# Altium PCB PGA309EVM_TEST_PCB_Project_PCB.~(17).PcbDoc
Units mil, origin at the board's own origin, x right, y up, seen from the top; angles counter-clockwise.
Board outline 6000 x 1500 mil, 2 copper layers (Top Layer, Bottom Layer), stack 62 mil thick; 101 components, 66 nets, 270 pads, 32 vias.
Unrouted connection lines stored in the file: 1.
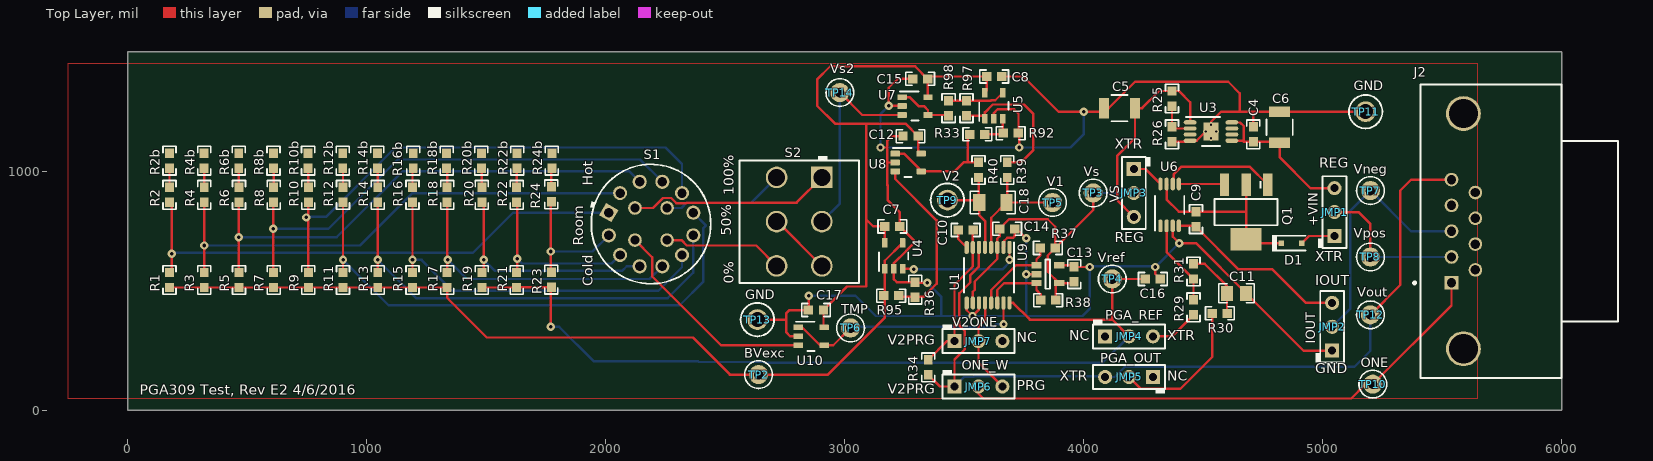
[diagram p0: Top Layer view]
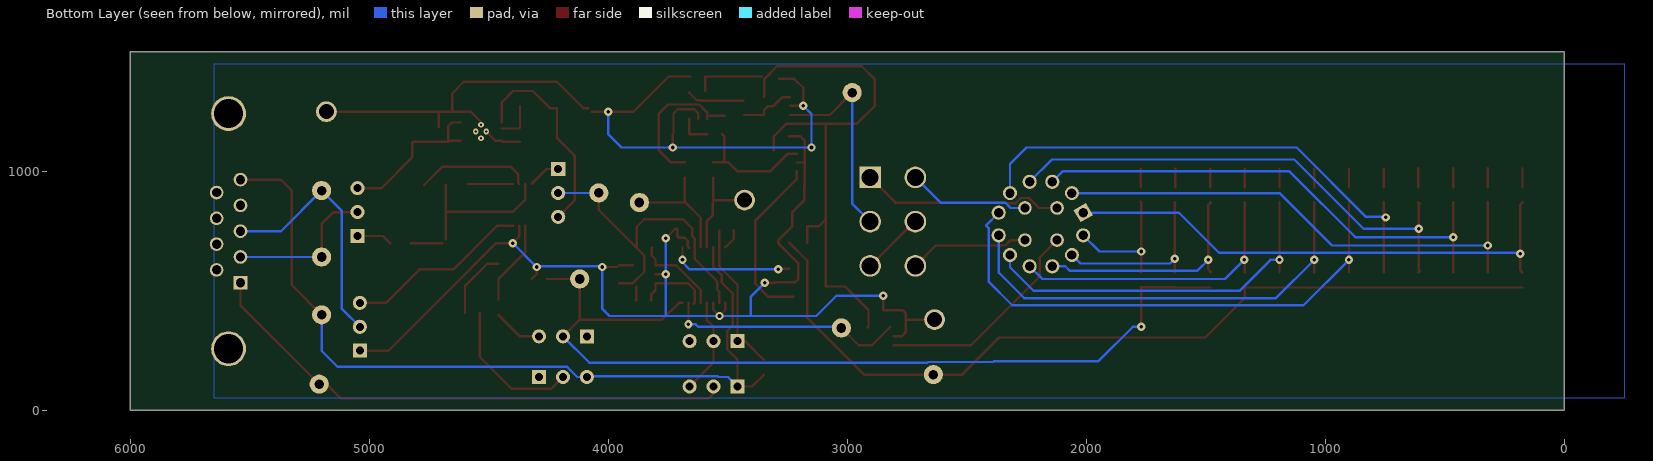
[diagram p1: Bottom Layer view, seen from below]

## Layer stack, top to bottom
Top Layer: signal copper 1.4
Dielectric: core 59.2, FR-4, Dk 4.8
Bottom Layer: signal copper 1.4

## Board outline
0,0 6000,0 6000,1500 0,1500

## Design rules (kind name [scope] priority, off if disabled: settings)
AcuteAngle [All] p1: minimum=4.50000000000000E+0001 checktracksonly=FALSE
AssemblyTestPointUsage [All] p1: valid=2
Clearance Clearance_Keepouts [((IsTrack Or IsArc) And Not InPoly) And IsFree and IsKeepOut vs ((IsTrack Or IsArc) And Not InPoly) And IsFree and IsKeepOut] p1: gap=0
Clearance Clearance_Poly [InPolygon] p2: gap=25
Clearance [All] p3: gap=7.87
ComponentClearance ComponentClearance_MountingHoles_FiducialMarks [InComponentClass('Mounting Holes') vs InComponentClass('FiducialMark')] p1: gap=50 collisioncheckmode=3 verticalgap=10 showdistances=FALSE
ComponentClearance ComponentClearance_Shunt [InComponentClass('Header') vs InComponentClass('Shunt')] p2: gap=0 collisioncheckmode=3 verticalgap=0 showdistances=FALSE
ComponentClearance ComponentClearance_Logo [InComponentClass('Logo')] p3: gap=50 collisioncheckmode=3 verticalgap=10 showdistances=FALSE
ComponentClearance ComponentClearance_ScrewToNut [(HasFootprint('NY PMS 440 0025 PH')) vs (HasFootprint('Keystone_1902C'))] p4: gap=5 collisioncheckmode=3 verticalgap=10 showdistances=FALSE
ComponentClearance ComponentClearance_MountingHoles [InComponentClass('Mounting Holes')] p5: gap=250 collisioncheckmode=3 verticalgap=100000 showdistances=FALSE
ComponentClearance ComponentClearance_SmallPassives [HasFootprint('0201*') or HasFootprint('0402*') or HasFootprint('0508') or HasFootprint('0603*') or HasFootprint('0612') or HasFootprint('0805*') or HasFootprint('0815*') or HasFootprint('0830*') or HasFootprint('1206*') or HasFootprint('1210*') or HasFootprint('1808*') or HasFootprint('1812*') or HasFootprint('1825*') or HasFootprint('2010*') or HasFootprint('2220*') or HasFootprint('2225*') or HasFootprint('2512*') or HasFootprint('2728*') or HasFootprint('3518*') vs HasFootprint('0201*') or HasFootprint('0402*') or HasFootprint('0508') or HasFootprint('0603*') or HasFootprint('0612') or HasFootprint('0805*') or HasFootprint('0815*') or HasFootprint('0830*') or HasFootprint('1206*') or HasFootprint('1210*') or HasFootprint('1808*') or HasFootprint('1812*') or HasFootprint('1825*') or HasFootprint('2010*') or HasFootprint('2220*') or HasFootprint('2225*') or HasFootprint('2512*') or HasFootprint('2728*') or HasFootprint('3518*')] p6: gap=14.96 collisioncheckmode=3 verticalgap=10 showdistances=FALSE
ComponentClearance ComponentClearance_THtoSMT [IsThruComponent vs IsSMTComponent] p7: gap=40 collisioncheckmode=3 verticalgap=30 showdistances=FALSE
ComponentClearance ComponentClearance_THtoTH [IsThruComponent vs IsThruComponent] p8: gap=30 collisioncheckmode=3 verticalgap=30 showdistances=FALSE
ComponentClearance [All] p9: gap=30 collisioncheckmode=3 verticalgap=10 showdistances=FALSE
DiffPairsRouting [All] p1: maxlimit=100 minlimit=10 mostfreqgap=10 maxuncoupledlength=1000
FabricationTestPointUsage TestPointUsage [All] p1: valid=2 allowmultiple=FALSE
FabricationTestpoint Testpoint [All] p1: side=3 testpointundercomponent=TRUE minsize=40 maxsize=100 preferedsize=60 minholesize=0 maxholesize=40 preferedholesize=32 testpointgrid=1 allowsidetop=TRUE allowsidebottom=TRUE usegrid=TRUE gridtolerance=0.01
FanoutControl Fanout_LCC [IsLCC] p1: bgadir=Out bgaviamode=Centered fanoutstyle=Auto fanoutdirection=Alternating viagrid=1 // Fanout_LCC (Default Rule)
FanoutControl Fanout_BGA [IsBGA] p2: bgadir=Out bgaviamode=Centered fanoutstyle=Auto fanoutdirection=Alternating viagrid=1 // Fanout_BGA (Default Rule)
FanoutControl Fanout_Default [All] p4: bgadir=Out bgaviamode=Centered fanoutstyle=Auto fanoutdirection=Alternating viagrid=1 // Fanout_Default (Default Rule)
FanoutControl Fanout_Small [(CompPinCount < 5)] p5: bgadir=Out bgaviamode=Centered fanoutstyle=Auto fanoutdirection=OutThenIn viagrid=1 // Fanout_Small (Default Rule)
HoleSize [All] p1: absolutevalues=TRUE maxlimit=251 minlimit=7.87 maxpercent=80.000 minpercent=20.000
MinimumAnnularRing MinimumAnnularRing_ThermalPadVias [IsVia and InAnyComponent] p1: minimumring=5.91
MinimumAnnularRing [All] p2: minimumring=8
MinimumSolderMaskSliver MinimumSolderMaskSliver_Logo [InComponentClass('Logo') vs InComponentClass('Logo')] p1: minsoldermaskwidth=0.7
MinimumSolderMaskSliver [All] p2: minsoldermaskwidth=3.94
PlaneConnect [All] p1: planeconnectstyle=Relief reliefexpansion=10 reliefentries=4 reliefconductorwidth=10 reliefairgap=10
PolygonConnect [All] p1: connectstyle=Relief reliefconductorwidth=10 reliefentries=4 polygonreliefangle="90 Angle" airgapwidth=10
RoutingVias ThermalPadVias [IsVia and InAnyComponent] p1: holewidth=7.87 width=19.68 viastyle="Through Hole" minholewidth=7.87 minwidth=19.68 maxholewidth=12.99 maxwidth=23.62
RoutingVias [All] p2: holewidth=16 width=34 viastyle="Through Hole" minholewidth=7.87 minwidth=26 maxholewidth=40 maxwidth=65
SilkToSilkClearance SilkToSilkClearance_Pb-FreeLogo [(HasFootprint('Pb-Free_Overlay_Medium') OR HasFootprint('Pb-Free_Overlay_Small')) vs (HasFootprint('Pb-Free_Overlay_Medium') OR HasFootprint('Pb-Free_Overlay_Small'))] p1: silktosilkclearance=0
SilkToSilkClearance [All] p2: silktosilkclearance=4
SilkscreenOverComponentPads SilkToComponentPadClearance [IsPad and InAnycomponent] p1: minsilkscreentomaskgap=5
SilkscreenOverComponentPads "Silk to Solder Mask Opening" [All] p2: minsilkscreentomaskgap=4
SolderMaskExpansion [All] p1: expansion=1.97
Width [All] p1: maxlimit=100 minlimit=6 preferedwidth=10 checkconnectedcopper=TRUE
14 further rules are at their usual default settings.

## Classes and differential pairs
component class Header: JMP1 JMP2 JMP3 JMP4 JMP5 JMP6 JMP7 JMP99

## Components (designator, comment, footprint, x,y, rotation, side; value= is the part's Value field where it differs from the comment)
C4 "C0603C104K5RACTU" 0603 4710,1155 r90 top
C5 "12103C106KAT2A" 1210_280 4150,1265 r180 top
C6 "12103C106KAT2A" 1210_280 4820,1185 r90 top
C7 "C0603C104K5RACTU" 0603 3200,770 r180 top
C8 "C0603C104K5RACTU" 0603 3625.87,1397.4 r0 top
C9 "C0603C103J5RACTU" 0603 4470,800 r270 top
C10 "06035A561JAT2A" 0603 3506.83,754.84 r0 top
C11 "08051C223JAT2A" 0805_HV 4640,490 r0 top
C12 "C0603C104K5RACTU" 0603 3275.87,1147.4 r0 top
C13 "C0603C104K5RACTU" 0603 3960.16,570 r270 top
C14 "C0603C104K5RACTU" 0603 3680,760 r180 top
C15 "C0603C104K5RACTU" 0603 3315.87,1387.4 r0 top
C16 "06033C101KAT2A" 0603 4290,550 r0 top
C17 "C0603C104K5RACTU" 0603 2880,420 r0 top
C18 "C3216C0G1E103J" 1206 3620,870 r180 top
D1 "ZHCS400TA" sod-323 4870,700 r0 top
J2 "09 65 162 6810" "Harting_09 65 162 6810" 6000,750 r90 top
JMP1 "+VIN" Mill-Max_800-10-003-10-001000 5050,830 r90 top
JMP2 "IOUT" Mill-Max_800-10-003-10-001000 5040,350 r90 top
JMP3 "VS" Mill-Max_800-10-003-10-001000 4210,910 r270 top
JMP4 "PGA_REF" Mill-Max_800-10-003-10-001000 4190,310 r0 top
JMP5 "PGA_OUT" Mill-Max_800-10-003-10-001000 4190,140 r180 top
JMP6 "ONE_W" Mill-Max_800-10-003-10-001000 3560,100 r0 top
JMP7 "V2ONE" Mill-Max_800-10-003-10-001000 3560,290 r0 top
Q1 "BCP55" SOT-223 4680,830 r270 top
R1 "CRCW060328K7FKEA" 0603 175.31,545.69 r90 top
R2 "CRCW06031K05FKEA" 0603 175.24,902.39 r270 top
R2b "0" 0603 175,1045 r270 top
R3 "CRCW060340K2FKEA" 0603 320.54,545.69 r90 top
R4 "CRCW06031K50FKEA" 0603 320.47,902.39 r270 top
R4b "0" 0603 320,1045 r270 top
R5 "CRCW060371K5FKEA" 0603 465.76,545.69 r90 top
R6 "CRCW06033K74FKEA" 0603 465.7,902.39 r270 top
R6b "0" 0603 465,1045 r270 top
R7 "CRCW060310K2FKEA" 0603 610.99,545.69 r90 top
R8 "CRCW06031K91FKEA" 0603 610.92,902.39 r270 top
R8b "0" 0603 610,1045 r270 top
R9 "RT0603BRD0719K3L" 0603 756.21,545.69 r90 top
R10 "CRCW06033K65FKEA" 0603 756.15,902.39 r270 top
R10b "0" 0603 755,1045 r270 top
R11 "CRCW060321K5FKEA" 0603 901.44,545.69 r90 top
R12 "CRCW06034K87FKEA" 0603 901.38,902.39 r270 top
R12b "0" 0603 900,1045 r270 top
R13 "CRCW060311K5FKEA" 0603 1046.67,545.69 r90 top
R14 "RT0603BRD074K37L" 0603 1046.6,902.39 r270 top
R14b "0" 0603 1045,1045 r270 top
R15 "CRCW060311K0FKEA" 0603 1191.89,545.69 r90 top
R16 "CRCW06034K22FKEA" 0603 1191.83,902.39 r270 top
R16b "0" 0603 1195,1045 r270 top
R17 "CRCW06031K05FKEA" 0603 1337.12,545.69 r90 top
R18 "RT0603BRD0723K4L" 0603 1337.05,902.39 r270 top
R18b "0" 0603 1335,1045 r270 top
R19 "CRCW060342K2FKEA" 0603 1482.35,545.69 r90 top
R20 "RT0603BRD077K96L" 0603 1482.28,902.39 r270 top
R20b "0" 0603 1480,1045 r270 top
R21 "RT0603BRD076K9L" 0603 1627.57,545.69 r90 top
R22 "CRCW06031K07FKEA" 0603 1627.51,902.39 r270 top
R22b "0" 0603 1630,1045 r270 top
R23 "CRCW060316K2FKEA" 0603 1772.8,546.99 r90 top
R24 "CPF0603B2K0E" 0603 1772.73,904 r270 top
R24b "0" 0603 1775,1045 r270 top
R25 "CRCW0603953KFKEA" 0603 4370,1305 r90 top
R26 "RT0603BRD07291KL" 0603 4370,1155 r90 top
R29 "CRCW0603191KFKEA" 0603 4460,431.5 r90 top
R30 "CRCW060311K3FKEA" 0603 4570,405.99 r0 top
R31 "CRCW060310K0FKEA" 0603 4460,581.5 r90 top
R33 "CRCW06031K00FKEA" 0603 3555,1155 r180 top
R34 "CRCW0603100RFKEA" 0603 3350,180 r270 top
R36 "CRCW060310K0FKEA" 0603 3295,505 r270 top
R37 "CRCW060310K0FKEA" 0603 3850,680 r0 top
R38 "CRCW060310K0FKEA" 0603 3851.81,461.3 r0 top
R39 "CRCW06031K00FKEA" 0603 3680.43,1006.14 r270 top
R40 "CRCW06031K00FKEA" 0603 3560.43,1006.14 r270 top
R92 "RT0603BRD07100KL" 0603 3695,1160 r0 top
R95 "CRCW060310K0FKEA" 0603 3195,480 r180 top
R97 "CRCW06031K00FKEA" 0603 3510,1265 r270 top
R98 "RT0603BRD07100KL" 0603 3435,1265 r270 top
S1 "56P30-01-4-03N" SW_56P30-01-4-03N 2190,780 r0 top
S2 "M2024SS1G03" SW_M2024 2810,790 r270 top
TP2 "BVexc" Keystone5000 2640,150 r0 top
TP3 "Vs" Keystone5000 4040,910 r0 top
TP4 "Vref" Keystone5000 4120,550 r0 top
TP5 "V1" Keystone5000 3870,870 r0 top
TP6 "TMP" Keystone5004 3025,345 r0 top
TP7 "Vneg" Keystone5004 5200,920 r0 top
TP8 "Vpos" Keystone5000 5200,642 r0 top
TP9 "V2" Keystone5006 3430,880 r0 top
TP10 "ONE" Keystone5000 5210,110 r0 top
TP11 "GND" Keystone5006 5180,1250 r0 top
TP12 "Vout" Keystone5000 5200,400 r0 top
TP13 "GND" Keystone5006 2635,380 r0 top
TP14 "Vs2" Keystone5000 2980,1330 r0 top
U1 "PGA309AIPWR" PW0016A_N 3600.43,566.14 r270 top
U3 "TPS7A1601DGNR" DGN0008C_N 4533,1167 r0 top
U4 "OPA333AMDBVREP" DBV0005A_N 3205.16,646.83 r90 top
U5 "OPA333AMDBVREP" DBV0005A_N 3624.45,1275.07 r90 top
U6 "XTR117AIDGKR" DGK0008A_N 4360,860 r90 top
U7 "OPA333AMDBVREP" DBV0005A_N 3294.8,1273.54 r0 top
U8 "OPA333AMDBVREP" DBV0005A_N 3265.87,1037.4 r0 top
U9 "24LC32AT-I/OT" SOT-23-5 3850.16,570 r0 top
U10 "OPA333AMDBVREP" DBV0005A_N 2860,310 r0 top

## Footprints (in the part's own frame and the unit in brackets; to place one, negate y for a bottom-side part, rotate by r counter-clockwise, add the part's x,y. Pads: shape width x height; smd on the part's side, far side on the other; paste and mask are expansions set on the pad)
0603 [mm] "0603 from SM-752 data"
  rect 1x0.95 smd: 1(-0.8,0) 2(0.8,0)
  silkscreen extent -1.52,-0.69 1.52,0.69, body extent -0.87,-0.47 0.87,0.47, height 1
0805_HV [mil] "0805 with 30mil clearance between pads"
  rect 50x63 smd: 1(-40,0) 2(40,0)
  silkscreen extent -74,-40 74,40, body extent -43,-29 43,29, height 57
1206 [mm] "1206 from SM-752 data"
  rect 1.3x1.85 smd: 1(-1.45,0) 2(1.45,0)
  silkscreen extent -2.4,-1.21 2.4,1.21, body extent -1.7,-0.9 1.7,0.9, height 1.35
1210_280 [mm] "SMD, 2-Leads, Body 3.6x2.8mm, Height 2.8mm"
  rect 1.1x2.2 smd: 1(-1.65,0) 2(1.65,0)
  silkscreen extent -0.84,-1.4 0.84,1.4, body extent -1.8,-1.4 1.8,1.4, height 2.8
DBV0005A_N [mm] "SOT23, 5-Leads, Body 2.9x1.6mm, Pitch 0.95mm, Lead Span 2.8mm, IPC Medium Density"
  rrect17% 1x0.6 smd: 1(-1.375,0.95) 2(-1.375,0) 3(-1.375,-0.95) 4(1.375,-0.95) 5(1.375,0.95)
  silkscreen extent -1.62,-1.55 0.38,1.55, body extent -1.42,-1.46 1.42,1.46, height 1.09
DGK0008A_N [mm] "TSOP, 8-Leads, Body 3x3mm, Pitch 0.65mm, IPC Medium Density"
  oval 1.35x0.45 smd: 1(-2.225,0.975) 2(-2.225,0.325) 3(-2.225,-0.325) 4(-2.225,-0.975) 5(2.225,-0.975) 6(2.225,-0.325) 7(2.225,0.325) 8(2.225,0.975)
  silkscreen extent -2.75,-1.55 0.95,1.55, body extent -2.45,-1.5 2.45,1.5, height 0.96
DGN0008C_N [mm] "TSOP, 8-Leads, Body 3x3mm, Pitch 0.65mm, Thermal Pad 1.98x1.88mm, IPC Medium Density"
  rrect100% 1.35x0.45 smd: 1(-2.225,0.975) 2(-2.225,0.325) 3(-2.225,-0.325) 4(-2.225,-0.975) 5(2.225,-0.975) 6(2.225,-0.325) 7(2.225,0.325) 8(2.225,0.975)
  rrect6% 1.6x1.918 smd: 9(0,0)
  silkscreen extent -2.65,-1.55 0.95,1.55, body extent -2.46,-1.5 2.46,1.5, height 1.1
"Harting_09 65 162 6810" [mm] "Harting"
  rect 1.45x1.45 hole 1 paste+0: 1(-5.48,11.7)
  round 1.45 hole 1 paste+0: 2(-2.74,11.7) 3(0,11.7) 4(2.74,11.7) 5(5.48,11.7) 6(-4.11,9.16) 7(-1.37,9.16) 8(1.37,9.16) 9(4.11,9.16)
  round 3.7 hole 3.1 paste+0: 10(-12.5,10.43) 11(12.5,10.43)
  silkscreen extent -15.6,-6 15.6,15.75, body extent -15.6,-6 15.6,15, height 13.6
Keystone5000 [mil] "For Keystone 500x miniature loop terminals"
  round 80 hole 40: 1(0,0)
  silkscreen extent -58,-58 58,58, body extent -49,-49 49,49, height 182
Keystone5004 [mil] "For Keystone 500x miniature loop terminals"
  round 80 hole 40: 1(0,0)
  silkscreen extent -58,-58 58,58, body extent -49,-49 49,49, height 182
Keystone5006 [mil] "Keystone Compact loops"
  round 87 hole 63: 1(0,0)
  silkscreen extent -70,-70 70,70, body extent -63,-63 62,63, height 225
Mill-Max_800-10-003-10-001000 [mm] "Mill-Max"
  rect 1.5x1.5 hole 0.85: 1(-2.54,0)
  round 1.5 hole 0.85: 2(0,0) 3(2.54,0)
  silkscreen extent -3.81,-1.27 3.81,1.78, body extent -3.81,-1.27 3.81,1.27, height 8.13
PW0016A_N [mm] "TSOP, 16-Leads, Body 5x4.4mm, Pitch 0.65mm, IPC Medium Density"
  oval 1.4x0.45 smd: 1(-2.95,2.275) 2(-2.95,1.625) 3(-2.95,0.975) 4(-2.95,0.325) 5(-2.95,-0.325) 6(-2.95,-0.975) 7(-2.95,-1.625) 8(-2.95,-2.275) 9(2.95,-2.275) 10(2.95,-1.625) 11(2.95,-0.975) 12(2.95,-0.325) 13(2.95,0.325) 14(2.95,0.975) 15(2.95,1.625) 16(2.95,2.275)
  silkscreen extent -3.5,-2.55 1.85,2.75, body extent -3.21,-2.5 3.21,2.5, height 1
sod-323 [mm] "NXP recommended land pattern"
  rect 0.6x0.6 smd paste-0.05: 1(-1.1,0) 2(1.1,0)
  silkscreen extent -2.06,-0.86 1.53,0.86, body extent -1.3,-0.67 1.3,0.68, height 1.1
SOT-23-5 [mm] "SOT23, 5-Leads, Body 2.9x1.6mm, Pitch 0.95mm, Lead Span 2.8mm, IPC Medium Density"
  rect 1.1x0.65 smd: 1(-1.2,0.95) 2(-1.2,0) 3(-1.2,-0.95) 4(1.2,-0.95) 5(1.2,0.95)
  silkscreen extent -0.25,-1.55 0.25,1.55, body extent -1.42,-1.46 1.42,1.46, height 1.08
SOT-223 [mm] "SOT223/SC73, 4-Leads, Body 6.5x3.5mm, Pitch 2.3mm, Lead Span 7mm, IPC Medium Density"
  rrect10% 2.4x1 smd: 1(-2.9,2.3) 2(-2.9,0) 3(-2.9,-2.3)
  rrect4% 2.4x3.3 smd: 4(2.9,0)
  silkscreen extent -3.33,-3.35 1.4,3.35, body extent -3.5,-3.25 3.5,3.25, height 1.62
SW_56P30-01-4-03N [mm] "TH, 16-Leads, Dia 12.7mm"
  rect 1.5x1.5 hole 1 rot 150: 1(-4.492,1.204)
  round 1.5 hole 1: 2(-3.288,3.288) 3(-1.204,4.492) 4(1.204,4.492) 5(3.288,3.288) 6(4.492,1.204) 7(4.492,-1.204) 8(3.288,-3.288) 9(1.204,-4.492) 10(-1.204,-4.492) 11(-3.288,-3.288) 12(-4.492,-1.204)
  round 1.45 hole 0.95: C1(-1.708,1.708) C2(1.708,1.708) C3(1.708,-1.708) C4(-1.708,-1.708)
  silkscreen extent -6.47,-6.35 6.35,6.35, body extent -6.35,-6.35 6.35,6.35, height 25.45
SW_M2024 [mm] "TH, 6-Leads, Body 13x12.7 mm, Pitch 4.7mm"
  rect 2.3x2.3 hole 1.8: 1(-4.7,2.4)
  round 2.3 hole 1.8: 2(0,2.4) 3(4.7,2.4) 4(-4.7,-2.4) 5(0,-2.4) 6(4.7,-2.4)
  silkscreen extent -7,-6.35 6.5,6.35, body extent -6.5,-6.35 6.5,6.35, height 29.51

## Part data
C4 C7 C8 C12 C13 C14 C15 C17: "CAP, CERM, 0.1 µF, 50 V, +/- 10%, X7R, 0603"
C5 C6: "CAP, CERM, 10 µF, 25 V, +/- 10%, X7R, 1210"
C9: "CAP, CERM, 0.01 µF, 50 V, +/- 5%, X7R, 0603"
C10: "CAP, CERM, 560 pF, 50 V, +/- 5%, C0G/NP0, 0603"
C11: "CAP, CERM, 0.022 µF, 100 V, +/- 5%, X7R, 0805"
C16: "CAP, CERM, 100 pF, 25 V, +/- 10%, X7R, 0603"
C18: "CAP, CERM, 0.01 µF, 25 V, +/- 5%, C0G/NP0, 1206"
D1: "Diode, Schottky, 40 V, 0.4 A, SOD-323"
J2: "D-Sub-9, 11Pos, Male, TH"
JMP1 JMP2 JMP3 JMP4 JMP5 JMP6 JMP7: library part 800-10-003-10-001000, "Header, 100mil, 3x1, TH"
Q1: library part "BCP55, Fairchild Semiconductor", "Transistor, NPN, 60 V, 1.5 A, SOT-223"
R1: "RES, 28.7 k, 1%, 0.1 W, 0603"
R2 R17: "RES, 1.05 k, 1%, 0.1 W, 0603"
R2b R4b R6b R8b R10b R12b R14b R16b R18b R20b R22b R24b: library part Resistor, "RES, xxx ohm, x%, xW, [PackageReference]"
R3: "RES, 40.2 k, 1%, 0.1 W, 0603"
R4: "RES, 1.50 k, 1%, 0.1 W, 0603"
R5: "RES, 71.5 k, 1%, 0.1 W, 0603"
R6: "RES, 3.74 k, 1%, 0.1 W, 0603"
R7: "RES, 10.2 k, 1%, 0.1 W, 0603"
R8: "RES, 1.91 k, 1%, 0.1 W, 0603"
R9: "RES, 19.3 k, 0.1%, 0.1 W, 0603"
R10: "RES, 3.65 k, 1%, 0.1 W, 0603"
R11: "RES, 21.5 k, 1%, 0.1 W, 0603"
R12: "RES, 4.87 k, 1%, 0.1 W, 0603"
R13: "RES, 11.5 k, 1%, 0.1 W, 0603"
R14: "RES, 4.37 k, 0.1%, 0.1 W, 0603"
R15: "RES, 11.0 k, 1%, 0.1 W, 0603"
R16: "RES, 4.22 k, 1%, 0.1 W, 0603"
R18: "RES, 23.4 k, 0.1%, 0.1 W, 0603"
R19: "RES, 42.2 k, 1%, 0.1 W, 0603"
R20: "RES, 7.96 k, 0.1%, 0.1 W, 0603"
R21: "RES, 6.90 k, 0.1%, 0.1 W, 0603"
R22: "RES, 1.07 k, 1%, 0.1 W, 0603"
R23: "RES, 16.2 k, 1%, 0.1 W, 0603"
R24: "RES, 2.00 k, 0.1%, 0.063 W, 0603"
R25: "RES, 953 k, 1%, 0.1 W, 0603"
R26: "RES, 291 k, 0.1%, 0.1 W, 0603"
R29: "RES, 191 k, 1%, 0.1 W, 0603"
R30: "RES, 11.3 k, 1%, 0.1 W, 0603"
R31 R36 R37 R38 R95: "RES, 10.0 k, 1%, 0.1 W, 0603"
R33 R39 R40 R97: "RES, 1.00 k, 1%, 0.1 W, 0603"
R34: "RES, 100, 1%, 0.1 W, 0603"
R92 R98: "RES, 100 k, 0.1%, 0.1 W, 0603"
S1: "Switch, 4P3T, 4Pole, 3 Pos, 0.2 A, 115 VAC, 30 VDC, TH"
S2: "Switch, Toggle SP3T, 0.4VA, 28V, TH"
TP2 TP3 TP4 TP5 TP8 TP10 TP12 TP14: library part 5000, "Test Point, Miniature, Red, TH"
TP6 TP7: library part 5004, "Test Point, Miniature, Yellow, TH"
TP9 TP11 TP13: library part 5006, "Test Point, Compact, Black, TH"
U1: "Voltage Output Programmable Sensor Conditioner, PW0016A"
U3: "Single Output LDO, 100 mA, Adjustable 1.2 to 18.5 V Output, 3 to 60 V Input, with Enable and Power Good, 8-pin MSOP (DGN), -40 to 125 degC, Green (RoHS & no Sb/Br)"
U4 U5 U7 U8 U10: "Enhanced Product, Micropower CMOS Operational Amplifier Zero-Drift Series, 1.8 to 5.5 V, -55 to 125 degC, 5-pin SOT23 (DBV0005A), Green (RoHS & no Sb/Br)"
U6: "4-20mA Current-Loop Transmitter, DGK0008A"
U9: "32K I2C™ Serial EEPROM, SOT-23-5"

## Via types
v1: diameter 35, hole 15, Top Layer to Bottom Layer, 28 vias
v2: diameter 24, hole 10, Top Layer to Bottom Layer, 4 vias

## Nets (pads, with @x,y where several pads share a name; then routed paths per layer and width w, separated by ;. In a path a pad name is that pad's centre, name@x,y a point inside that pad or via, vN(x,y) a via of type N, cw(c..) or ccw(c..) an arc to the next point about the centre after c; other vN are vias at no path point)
0%: S1.C3 S2.6 | length 502.9
  Top Layer w10: S1.C3 2317.19,712.77 2339.75,690.22 2630.26,690.22 S2.6
50%: S1.C2 S2.4 | length 511.2
  Bottom Layer w10: S1.C2 2317.19,847.23 2339.75,869.78 2610.26,869.78 S2.4
100%: S1.C1 S2.1 | length 852.6
  Top Layer w10: S1.C1 2198.66,847.23 2240.07,888.65 2274.39,888.65 2295.98,867.05 2337.01,867.05 2339.75,869.78 2799.23,869.78 S2.1
BUFTEMP: TP6.1 U1.15 U10.1 U10.4 | length 1003.5
  Top Layer w10: U10.1@2820,350 2897.4,272.6 U10.4 2952.6,272.6 TP6.1 ; U1.15 3665,449.41 v1(3665,360)
  Bottom Layer w10: TP6.1 3030,350 3625,350 3635,360 v1(3665,360)
BUFVEXC: R1.1 R3.1 R5.1 R7.1 R9.1 R11.1 R13.1 R15.1 R17.1 R95.2 TP2.1 U4.1 U4.4 | length 3611.1
  Top Layer w10: R1.1 R3.1 R5.1 R7.1 R9.1 R11.1 R13.1 R15.1 R17.1 1337.12,470.51 1502.63,305 2365,305 2520,150 TP2.1 2930,150 3168.51,388.51 3168.51,510 ; 3167.76,510.75 U4.1 3167.76,626.16 U4.4
COLD_0%: R13.2 R14.2 S1.7 | length 1880.2
  Top Layer w10: R13.2@1046.6,577.25 v1(1046.6,630) R14.2
  Bottom Layer w10: v1(1046.6,630) 1206.6,470 2260,470 2366.83,576.83 S1.7
COLD_50%: R7.2 R8.2 S1.4 | length 2088.8
  Top Layer w10: R7.2@610.92,577.25 605,583.18 610,588.18 v1(610,760) 610,859.97 605,864.97 R8.2
  Bottom Layer w10: v1(610,760) 840,760 1130,1050 2144.21,1050 S1.4
COLD_100%: R1.2 R2.2 S1.1 | length 2196.4
  Top Layer w10: R1.2@175.24,577.25 175,577.5 185,587.5 v1(185,655) 185,860.65 175,870.65 R2.2
  Bottom Layer w10: v1@189.63,659.63 888.05,659.63 888.79,660.37 913.96,660.37 914.33,660 1033.65,660 1034.02,660.37 1059.18,660.37 1059.56,660 1178.87,660 1179.25,660.37 1204.41,660.37 1204.78,660 1327.04,660 1327.42,660.37 1352.58,660.37 1352.96,660 1445,660 1612.38,827.38 S1.1
GND: C4.2 C5.2 C6.2 C7.1 C8.2 C11.2 C12.1 C13.1 C14.1 C15.1 C16.2 C17.1 J2.4 J2.10 J2.11 JMP2.1 R2b.1 R4b.1 R6b.1 R8b.1 R10b.1 R12b.1 R14b.1 R16b.1 R18b.1 R20b.1 R22b.1 R24b.1 R26.1 R36.1 R92.2 TP11.1 TP13.1 U1.2 U1.9 U1.11 U3.4 U3.9 U4.2 U5.2 U6.3 U7.2 U8.2 U9.2 U9.5 U10.2 | length 8864.3
  Top Layer w10: TP13.1 2755,380 ; U10.2 2772.63,310 2755,327.63 2755,380 ; C17.1 2770,420 2755,405 2755,380 ; C17.1@2850,421.5 v1(2850,480) ; v1(3150,1100) 3179.17,1100 ; v1(3185,1275) 3185,1350 3222.4,1387.4 C15.1 ; v1@3192.4,1275 U7.2@3239.21,1275 ; U8.2 3182.4,1037.4 3179.17,1034.17 ; C12.1 3197.4,1147.4 3179.17,1129.17 3179.17,1034.17 ; R36.1@3296.49,535 v1(3345,535) ; R36.1@3300,536.49 R36.1 3218.51,536.49 3205.16,549.84 U4.2 3205.16,615.16 3258.41,668.41 3258.53,668.41 3267.24,677.12 3267.24,677.24 3290,700 3290,711.5 C7.1 3231.5,828.5 3180,880 3180,942.16 3179.17,942.99 3179.17,1034.17 ; U1.9 3510.87,419.13 v1(3535,395) 3562.05,422.05 U1.11 ; U5.2 3624.45,1244.45 3640,1260 3710,1260 3727.36,1242.64 R92.2@3727.36,1157.4 ; C8.2 3747.6,1397.4 3895,1250 v1(4000,1250) C5.2@4070.04,1250 ; U1.2@3662.13,680 U1.2 3668.27,686.14 3668.27,709.99 3681,722.72 3704.84,722.72 3711.5,729.37 C14.1 3720,760 v1(3760,720) ; v1(3730,1100) R92.2@3730,1154.76 ; v1(3760,570) U9.2 ; U9.5 C13.1@3954.25,607.4 ; C13.1@3961.65,600 v1(4025,600) ; C5.2 4105,1265 4215,1375 4605,1375 4653.5,1326.5 4653.5,1249.96 ; v1(4300,600) 4300,571.5 C16.2 ; R26.1 4440.29,1123.5 U3.4 4472.96,1128.61 v2(4511.35,1167) ; U6.3 4372.8,727.2 v1(4400,700) 4470,700 C11.2 4920,250 JMP2.1 ; v2(4533,1194.95) 4533,1208 4574.96,1249.96 4653.5,1249.96 ; C4.2 4710,1249.96 ; TP11.1 C6.2 C6.2 4710,1249.96 ; 4653.5,1249.96 4710,1249.96
  Bottom Layer w10: v1(2850,480) 3045,480 3130,395 3405,395 ; v1(3185,1275) 3150,1240 v1(3150,1100) v1(3730,1100) 3945,1100 4000,1155 v1(4000,1250) ; v1(3345,535) 3405,475 3405,395 ; v1(3760,720) v1(3760,570) 3760,395 ; v1(4400,700) 4302.87,602.87 4027.87,602.87 v1(4025,600) 4025,425 3995,395 3760,395 ; 3405,395 v1(3535,395) 3760,395
  other v2: 4533,1139.05 4554.65,1167
HOT_0%: R17.2 R18.2 S1.9 | length 1246.2
  Top Layer w10: R17.2@1337.06,577.25 R18.2
  Bottom Layer w10: v1(1340,630) 1420,550 2184.21,550 S1.9
HOT_50%: R11.2 R12.2 S1.6 | length 2240.1
  Top Layer w10: R11.2@901.38,577.25 v1(901.38,630) R12.2
  Bottom Layer w10: v1(901.38,630) 1091.38,440 2310,440 2409.23,539.23 2409.23,763.45 2420,774.21 S1.6 S1.6@2366.83,823.17
HOT_100%: R5.2 R6.2 S1.3 | length 2102.3
  Top Layer w10: R5.2@465.7,577.25 v1(465.7,725) R6.2
  Bottom Layer w10: v1(465.7,725) 875,725 1150,1000 2099.45,1000 S1.3
NetC4_1: C4.1 C6.1 JMP1.3 U3.5 U3.8 | length 662.7
  Top Layer w10: U3.5 4668.61,1128.61 4670,1130 ; U3.8 4620.98,1205 4655,1205 4670,1190 4670,1130 ; C6.1@4816.54,1123.5 C4.1 4670,1123.5 4670,1130 ; C6.1 4820,1060 4950,930 JMP1.3
NetC5_1: C5.1 JMP3.3 R25.2 U3.1 | length 878.7
  Top Layer w10: JMP3.3 4140,880 4140,1065 4214.96,1139.96 C5.1 4245,1265 4316.5,1336.5 R25.2 4398.5,1336.5 4445.4,1289.6 U3.1
NetC9_1: C9.1 D1.1 Q1.2 Q1.4 U6.7 | length 784.1
  Top Layer w10: U6.7@4351.06,943.74 U6.7 4347.2,882.8 4398.5,831.5 C9.1 4678.5,831.5 4680,830 ; Q1.4 4680,830 ; Q1.2 4680,830 ; Q1.4@4695.83,700 D1.1
NetC9_2: C9.2 JMP2.3 U6.4 | length 775.2
  Top Layer w10: U6.4 4466.1,772.4 C9.2 4648.5,590 4790,590 4930,450 JMP2.3
NetC10_1: C10.1 U1.8 | length 87.3
  Top Layer w10: C10.1 3475.34,717.82 U1.8
NetC10_2: C10.2 JMP7.1 R34.1 U1.7 | length 637.2
  Top Layer w10: R34.1 3428.5,290 JMP7.1 3460,525.83 3536.46,602.29 U1.7 C10.2@3536.46,752.97
NetC11_1: C11.1 R30.2 R31.2 | length 291
  Top Layer w10: R31.2 4507.01,612.99 4600,520 C11.1 R30.2@4600,407.49
NetC18_1: C18.1 R39.2 TP5.1 U1.4 | length 508.4
  Top Layer w10: U1.4 3613.23,806.14 C18.1 TP5.1 ; C18.1@3680.43,873.35 R39.2
NetC18_2: C18.2 R40.2 TP9.1 U1.5 | length 423
  Top Layer w10: TP9.1 C18.2@3552.91,880 ; C18.2@3560.43,872.48 R40.2 ; C18.2 3562.91,817.09 3587.64,792.36 U1.5
NetD1_2: D1.2 JMP1.1 | length 149.1
  Top Layer w10: D1.2 4943.31,730 JMP1.1
NetJMP3_1: JMP3.1 U6.8 | length 137.5
  Top Layer w10: JMP3.1 4259.21,1010 U6.8
NetJMP4_3: JMP4.3 R29.1 | length 207.3
  Top Layer w10: JMP4.3 4370,310 R29.1
NetJMP5_2: JMP5.2 R30.1 | length 606.7
  Top Layer w10: JMP5.2 4240,90 4404.5,90 4538.5,224.01 R30.1
NetJMP6_3: JMP6.3 JMP7.2 U1.12 | length 402.9
  Top Layer w10: U1.12 3587.64,377.64 3560,350 JMP7.2 3560,200 JMP6.3
NetQ1_1: Q1.1 U6.6 | length 479.8
  Top Layer w10: U6.6 4376.65,951.46 4376.65,986.65 4410,1020 4694.73,1020 Q1.1
NetQ1_3: Q1.3 U6.5 | length 187.6
  Top Layer w10: U6.5 Q1.3@4586.02,947.6
NetR2_1: R2.1 R2b.2 | length 79.4
  Top Layer w10: R2.1 R2b.2@175.24,1013.26
NetR4_1: R4.1 R4b.2 | length 79.2
  Top Layer w10: R4.1 R4b.2@320.47,1013.03
NetR6_1: R6.1 R6b.2 | length 78.9
  Top Layer w10: R6.1 R6b.2@465.7,1012.81
NetR8_1: R8.1 R8b.2 | length 78.7
  Top Layer w10: R8.1 R8b.2@610.92,1012.58
NetR10_1: R10.1 R10b.2 | length 78.5
  Top Layer w10: R10.1 R10b.2@756.15,1012.35
NetR12_1: R12.1 R12b.2 | length 78.2
  Top Layer w10: R12.1 R12b.2@901.38,1012.13
NetR14_1: R14.1 R14b.2 | length 78
  Top Layer w10: R14.1 R14b.2@1046.6,1011.9
NetR16_1: R16.1 R16b.2 | length 76.4
  Top Layer w10: R16.1 R16b.2@1191.83,1010.33
NetR18_1: R18.1 R18b.2 | length 77.6
  Top Layer w10: R18.1 R18b.2@1337.06,1011.45
NetR20_1: R20.1 R20b.2 | length 77.3
  Top Layer w10: R20.1 R20b.2@1482.28,1011.22
NetR22_1: R22.1 R22b.2 | length 77.1
  Top Layer w10: R22.1 R22b.2@1627.51,1011.01
NetR24_1: R24.1 R24b.2 | length 75.7
  Top Layer w10: R24.1 R24b.2@1772.73,1011.24
NetR25_1: R25.1 R26.2 U3.2 | length 160.6
  Top Layer w10: R26.2@4370,1181.65 R26.2 R25.1 ; R26.2@4376.7,1179.8 U3.2
NetR29_2: R29.2 R31.1 U6.2 | length 356.1
  Top Layer w10: U6.2 4347.2,662.8 R31.1 R29.2
NetR33_1: R33.1 R92.1 U5.3 | length 138
  Top Layer w10: R33.1 R92.1@3660.2,1155 ; R92.1@3661.85,1156.65 U5.3
NetR33_2: R33.2 R40.1 U8.1 U8.4 | length 518.1
  Top Layer w10: U8.1 3248.46,1074.8 3320,1003.27 U8.4 3460,1000 3497.64,1037.64 3515,1037.64 ; R33.2 3515,1146.5 3515,1037.64 ; R40.1 3515,1037.64
NetR36_2: R36.2 R95.1 U8.3 | length 723.1
  Top Layer w10: U8.3 3211.73,968.27 3385,795 3385,530 3330,475 R95.1@3226.5,475
NetR37_1: R37.1 U1.13 U9.1 | length 365.1
  Top Layer w10: U1.13 3613.23,503.27 3717.36,607.4 U9.1 3802.91,632.91 3818.5,648.5 R37.1
NetR38_1: R38.1 U1.14 U9.3 | length 313.7
  Top Layer w10: U1.14@3642.68,446.14 U1.14 3638.82,503.59 3667.83,532.6 U9.3 3802.91,503.46 3820.32,486.06 R38.1
NetR39_1: R39.1 R97.2 U5.1 | length 602.2
  Top Layer w10: R97.2@3514.45,1233.57 3574.41,1233.57 ; U5.1@3585.87,1219.75 U5.1 3587.05,1247.05 3620,1280 3750,1280 3790,1240 3790,1090 3737.64,1037.64 R39.1
NetR97_1: R97.1 R98.1 U5.4 | length 240.3
  Top Layer w10: R98.1 R97.1@3514.38,1296.5 ; R97.1@3514.45,1296.57 3611.29,1296.57 3612.6,1297.87 3630.52,1297.87 U5.4
NetR98_2: R98.2 U7.1 U7.4 | length 234.3
  Top Layer w10: U7.1 3272.03,1310.95 3309.43,1273.54 3331.46,1273.54 3348.94,1256.06 U7.4 R98.2@3432.36,1236.14
NetS2_2: S2.2 TP14.1 U7.3 | length 870.8
  Top Layer w10: TP14.1 3073.86,1236.14 U7.3
  Bottom Layer w10: S2.2 2980,865.51 TP14.1
NetS2_3: S2.3 S2.5 | length 265.6
  Top Layer w10: S2.5 2719.45,790 S2.3
NetU1_1: U1.1 U4.3 | length 519.5
  Top Layer w10: U4.3 v1@3287.3,592.7 ; v1(3690,630) U1.1
  Bottom Layer w10: v1(3290,590) 3660,590 3690,620 v1(3690,630)
ONE-WIRE: J2.1 JMP6.2 TP10.1 | length 2273.8
  Top Layer w10: JMP6.2 3560,70 3580,50 5120,50 5180,110 TP10.1 5539.37,439.37 J2.1
ROOM_0%: R15.2 R16.2 S1.8 | length 1567.4
  Top Layer w10: R15.2@1191.83,577.25 v1(1191.83,630) R16.2
  Bottom Layer w10: v1(1191.83,630) 1230,630 1360,500 2220,500 2319.45,599.45 S1.8
ROOM_50%: R9.2 R10.2 S1.5 | length 2126.9
  Top Layer w10: R9.2@756.15,577.25 756.15,810 R10.2
  Bottom Layer w10: v1@756.15,810 830,810 1120,1100 2250,1100 2319.45,1030.55 S1.5
  other v1: 747.31,807.52
ROOM_100%: R3.2 R4.2 S1.2 | length 2124.6
  Top Layer w10: R3.2@320.47,577.25 v1(320.47,690) R4.2
  Bottom Layer w10: v1(320.47,690) 972.71,690 1192.16,909.45 S1.2
T_COLD: R19.2 R20.2 S1.10 | length 982.6
  Top Layer w10: R19.2@1482.28,577.25 1480,579.53 1490,589.53 v1(1490,630) 1490,858.61 1480,868.61 R20.2
  Bottom Layer w10: v1(1490,630) 1535,585 2070,585 2088.17,603.17 S1.10
T_HOT: R23.2 R24.2 S1.12 | length 567.4
  Top Layer w10: R23.2@1772.73,578.55 1770,581.29 v1(1770,665) 1770,869.77 R24.2
  Bottom Layer w10: v1(1770,665) 1945.55,665 S1.12
T_ROOM: R21.2 R22.2 S1.11 | length 749.3
  Top Layer w10: R21.2@1627.51,577.25 1630,579.74 v1(1630,635) 1630,868.4 R22.2
  Bottom Layer w10: v1(1630,635) 1650,615 2025,615 S1.11
TEMP: S1.C4 U10.3 | length 912.2
  Top Layer w10: S1.C4 2194.98,640.56 2194.98,560.77 2483.15,272.6 U10.3
VNEG: J2.3 JMP2.2 TP7.1 | length 1046.1
  Bottom Layer w10: JMP2.2 5115,425 5115,835 TP7.1 5370,750 J2.3
VOUT: J2.5 JMP5.3 JMP6.1 R34.2 TP12.1 U1.6 | length 3533.8
  Top Layer w10: R34.2 3398.5,100 JMP6.1 3460,212.74 3502.4,255.14 3502.4,332.4 3480,354.8 3480,490 3526.3,536.3 3526.3,566.86 3562.05,602.6 U1.6 ; TP12.1 5325,525 5325,920 5370.75,965.75 J2.5
  Bottom Layer w10: JMP6.1 3500,140 3540.04,140 3542.44,142.4 4090,142.4 JMP5.3 4130.04,140 4172.44,182.4 5132.4,182.4 5200,250 TP12.1
VPOS: J2.2 JMP1.2 TP8.1 | length 648.1
  Top Layer w10: JMP1.2 5150,830 5200,780 TP8.1
  Bottom Layer w10: TP8.1 5539.24,642 J2.2
VREF: C16.1 JMP4.2 R19.1 R21.1 R23.1 TP4.1 U1.16 | length 3851.8
  Top Layer w10: R19.1 R21.1 1628.87,515.49 R23.1 1770,512.69 v1(1770,350) ; U1.16 3705,450 3775,380 4120,380 ; JMP4.2 4120,380 ; C16.1 TP4.1 4120,380
  Bottom Layer w10: v1(1770,350) 1805.6,350 1949.23,206.37 2386.22,206.37 2389.72,202.87 2661.9,202.87 2664.78,200 4080,200 JMP4.2
VS: C7.2 C8.1 C12.2 C13.2 C14.2 C15.2 C17.2 JMP3.2 R37.2 R38.2 TP3.1 U1.3 U1.10 U4.5 U5.5 U7.5 U8.5 U9.4 U10.5 | length 4125.9
  Top Layer w10: U10.5 2911.5,350.04 C17.2 3010,518.5 3090,518.5 3090,800 ; U4.5@3168.5,701.71 C7.2 3120,770 3090,800 ; 3307.36,1087.44 C12.2 3254.76,1200 3090,1200 ; U7.5@3347.36,1312.52 C15.2 3294.76,1440 2940,1440 2885,1385 2885,1275 2960,1200 3090,1200 ; C15.2@3357.36,1397.4 C8.1 U5.5@3594.37,1336.52 ; U1.10 3536.46,496.46 3544.17,504.17 3544.17,539.17 3638.82,633.82 U1.3 3638.82,718.82 3648.5,728.5 C14.2 3688.5,800 3850,800 3881.5,768.5 R37.2 ; R38.2 3883.31,518.5 ; C13.2@3954.25,532.6 U9.4 3850,580 3850,648.5 R37.2 ; TP3.1 4040,838.5 R37.2 ; 3090,800 3090,1200
  Bottom Layer w10: TP3.1 JMP3.2
pads on no net: J2.6 J2.7 J2.8 J2.9 JMP4.1 JMP5.1 JMP7.3 U3.3 U3.6 U3.7 U6.1

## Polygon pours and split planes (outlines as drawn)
GND on Top Layer "TOP_LAYER_GND_P020" (solid, remove dead copper, shelved, pour order 20): -250,1450 -250,50 5650,50 5650,1450 -250,1450
GND on Bottom Layer "BOTTOM_LAYER_GND_P022" (solid, remove dead copper, shelved, pour order 22): -250,1450 -250,50 5650,50 5650,1450 -250,1450

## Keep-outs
Keep-Out Layer:
  text ".Layer_Name" at 277,-858.49 h60

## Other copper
Top Layer:
  text ".Layer_Name" at 277,-858.49 h60
Bottom Layer:
  text ".Layer_Name" at 277,-858.49 h60

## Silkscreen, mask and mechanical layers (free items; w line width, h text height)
Top Overlay:
  text "XTR" at 4130,1080 h72.83
  text "REG" at 4985,1000 h72.83
  text "Hot" at 1960,940 h72.83 r90
  text "100%" at 2550,900 h72.83 r90
  text "50%" at 2540,730 h72.83 r90
  text "Room" at 1920,690 h72.83 r90
  text "REG" at 4130,690 h72.83
  text "XTR" at 4970,610 h72.83
  text "0%" at 2550,530 h72.83 r90
  text "Cold" at 1960,520 h72.83 r90
  text "IOUT" at 4970,510 h72.83
  text "NC" at 3940,280 h72.83
  text "XTR" at 4350,280 h72.83
  text "NC" at 3720,270 h72.83
  text "V2PRG" at 3180,260 h72.83
  text "GND" at 4970,140 h72.83
  text "XTR" at 3900,110 h72.83
  text "NC" at 4350,110 h72.83
  text "PRG" at 3720,70 h72.83
  text "V2PRG" at 3180,55 h72.83
  text "PGA309 Test, Rev E2 4/6/2016" at 50,50 h72.83
  text ".Layer_Name" at 277,-858.49 h60
Bottom Overlay:
  text ".Layer_Name" at 277,-858.49 h60
Top Paste:
  text ".Layer_Name" at 277,-858.49 h60
Bottom Paste:
  text ".Layer_Name" at 277,-858.49 h60
Top Solder:
  text ".Layer_Name" at 277,-858.49 h60
  text ".Layer_Name" at 277,-858.49 h60
Bottom Solder:
  text ".Layer_Name" at 277,-858.49 h60
Drill Guide:
  text ".Layer_Name" at 277,-858.49 h60
M1 Board Outline:
  the board outline again, w10
  text ".Layer_Name" at 277,-858.49 h60
M2 Board Dimensions:
  rectangle: 0,-275 125,-150
  rectangle: 125,-400 500,-275
  lines w7: 0,-275 1000,-275 ; 125,-400 125,-150 ; 250,-400 250,-150 ; 500,-400 500,-150 ; 750,-400 750,-150 ; 0,-400 1000,-400 1000,-150 0,-150 0,-400
  lines w10: -320,60 -300,0 ; -320,1440 -300,1500 ; -310,0 -290,0 ; -310,1500 -290,1500 ; -300,474.08 -300,0 ; -300,1025.92 -300,1500 ; -280,60 -300,0 ; -280,1440 -300,1500 ; 0,1790 0,1810 ; 60,1780 0,1800 ; 60,1820 0,1800 ; 2719.09,1800 0,1800 ; 3280.91,1800 6000,1800 ; 5940,1780 6000,1800 ; 5940,1820 6000,1800 ; 6000,1790 6000,1810
  text "6000 (mil)" at 2729.09,1764.01 h60
  text "1500 (mil)" at -264.01,484.08 h60 r90
  text ".Layer_Name" at 277,-858.49 h60
M3 3D STEP Top:
  text ".Layer_Name" at 277,-858.49 h60
M4 3D STEP Bottom:
  text ".Layer_Name" at 277,-858.49 h60
M5 Assembly Top:
  lines w10: -592,-930.17 6008,-930.17 ; -592,-726.83 6010,-726.83 ; -592,-523.5 -592,-1133.5 3413,-1133.5 6010,-1133.5 6010,-523.5 -591.5,-523.5 -591.5,-1133.5 984,-1133.5 ; 1873,-1133.5 1873,-523.5 ; 3140,-726.83 3140,-523.5 ; 3980,-726.83 3980,-523.5 ; 4602,-1140 4602,-937.17
  text "COMPONENTS MARKED 'DNP' SHOULD NOT BE POPULATED." at 853.5,-318.5 h60
  text "ASSEMBLY VARIANT:" at 853,-434 h60
  text ".VariantName" at 1889,-434 h60
  text "PCB VIEWED FROM TOP SIDE" at -528.5,-655.67 h60
  text "BOARD #:" at 1948,-655.67 h60
  text ".PRJ_Number" at 2493.5,-655.67 h60
  text "REV:" at 3338,-655.67 h60
  text ".PCB_Rev" at 3629.5,-655.67 h60
  text "SVN REV:" at 4176,-655.67 h60
  text ".VersionControl_RevNumber" at 4682,-655.67 h60
  text "TID #:" at 1948,-859 h60
  text ".TID" at 2493.5,-859 h60
  text "PLOT NAME =" at -528.5,-1064.34 h60
  text ".plot_File_Name" at 277,-1064.34 h60
  text "GENERATED    :" at 1950,-1064.34 h60
  text ".Print_Date" at 2819.5,-1064.34 h60
  text ".Print_Time" at 3548.5,-1064.34 h60
  text "TEXAS INSTRUMENTS" at 4813,-1064.34 h60
M6 Assembly Bottom:
  lines w10: -592.5,-727.33 6009.5,-727.33 ; -590.5,-930.67 6009.5,-930.67 ; 815.5,-1140.5 815.5,-937.67 ; 1437.5,-727.33 1437.5,-524 ; 2277.5,-727.33 2277.5,-524 ; 3544.5,-1134 3544.5,-524 ; 4433.5,-1134 6009,-1134 6009,-524 -592.5,-524 -592.5,-1134 2004.5,-1134 6009.5,-1134 6009.5,-524
  text "COMPONENTS MARKED 'DNP' SHOULD NOT BE POPULATED." at 5802,-318 h60
  text ".VariantName" at 4758,-434 h60
  text "ASSEMBLY VARIANT:" at 5797,-434 h60
  text ".VersionControl_RevNumber" at 735.5,-656.17 h60
  text "SVN REV:" at 1241.5,-656.17 h60
  text ".PCB_Rev" at 1788,-656.17 h60
  text "REV:" at 2079.5,-656.17 h60
  text ".PRJ_Number" at 2924,-656.17 h60
  text "BOARD #:" at 3469.5,-656.17 h60
  text "PCB VIEWED FROM BOTTOM SIDE" at 5946,-656.17 h60
  text ".TID" at 2924,-859.5 h60
  text "TID #:" at 3469.5,-859.5 h60
  text "TEXAS INSTRUMENTS" at 604.5,-1064.84 h60
  text ".Print_Time" at 1869,-1064.84 h60
  text ".Print_Date" at 2598,-1064.84 h60
  text "GENERATED    :" at 3467.5,-1064.84 h60
  text ".plot_File_Name" at 5140.5,-1064.84 h60
  text "PLOT NAME =" at 5946,-1064.84 h60
M9 Title Sheet:
  drawing of 57 lines, arcs and shapes, not listed
  text "1" at 439.84,8036.5 h70
  text "2" at 2935.5,8036.5 h70
  text "3" at 5424.84,8036.5 h70
  text "4" at 7931.51,8036.5 h70
  text "5" at 10430.5,8036.5 h70
  text "6" at 12935.5,8036.5 h70
  text "A" at -716.5,6893.5 h70
  text "A" at 14083.5,6893.5 h70
  text "B" at -716.5,4513.5 h70
  text "B" at 14083.5,4513.5 h70
  text "C" at -716.5,2138.5 h70
  text "C" at 14083.5,2138.5 h70
  text "PROJECT TITLE:" at 11043.5,277.5 h45
  text ".PRJ_Title" at 11093.5,144.17 h70
  text "DESIGNED FOR:" at 11043.5,-23.5 h45
  text ".PRJ_Customer" at 11093.5,-163.5 h70
  text "D" at -716.5,-231.5 h70
  text "D" at 14083.5,-231.5 h70
  text "FILE NAME:" at 11043.5,-323.5 h45
  text ".PCB_File_Name_No_Path" at 11093.5,-443.5 h70
  text "Texas Instruments (TI) and/or its licensors do not warrant the accuracy or completeness of this specification" at 6074,-605.34 h45
  text "ENGINEER:" at 11043.5,-613.5 h45
  text "LAYOUT BY:" at 12548.5,-613.5 h45
  text "or any information contained therein. TI and/or its licensors do not warrant that this design will meet" at 6029.01,-718 h45
  text ".PRJ_Engineer" at 11093.5,-768.49 h70
  text ".PCB_Layout" at 12599,-768.49 h70
  text "the specifications, will be suitable for your application or fit for any particular purpose, or will operate in" at 6029.01,-830.67 h45
  text ".Layer_Name" at 277,-858.49 h60
  text "ALTIUM DESIGNER VERSION:" at 12548.5,-923.5 h45
  text "an implementation. TI and/or its licensors do not warrant that the design is production worthy. You should" at 6029.01,-943.33 h45
  text "completely validate and test your design implementation to confirm the system functionality for your application." at 6074,-1056 h45
  text ".print_Scale" at 11093.5,-1056.83 h70
  text ".Application_BuildNumber" at 12599,-1056.83 h70
  text "1" at 439.84,-1263.5 h70
  text "2" at 2935.5,-1263.5 h70
  text "3" at 5424.84,-1263.5 h70
  text "4" at 7931.51,-1263.5 h70
  text "5" at 10430.5,-1263.5 h70
  text "6" at 12935.5,-1263.5 h70
M10 Fab Notes:
  drawing of 173 lines, arcs and shapes, not listed
  text "DESIGN INFORMATION" at 12078.02,6201 h60
  text "MIN. TRACK WIDTH:" at 11433.46,6021 h60
  text "8" at 12529.7,6021 h60
  text "MIL" at 12684.46,6021 h60
  text "MIN. CLEARANCE:" at 11433.46,5889 h60
  text "0.2" at 12469.7,5889 h60
  text "mm" at 12684.46,5889 h60
  text "MIN. VIA PAD SIZE:" at 11433.46,5757 h60
  text "24" at 12499.71,5757 h60
  text "MIL" at 12684.46,5757 h60
  text "0.05mm (2MIL)" at 12128.46,5615.29 h60
  text "MINIMUM ANNULAR RING" at 11104.23,5611 h60
  text "EXTERNAL" at 12836.46,5611 h60
  text "PER" at 11304.23,5493 h60
  text "IPC-D-275 CLASS 2 LEVEL C" at 11524.23,5493 h60
  text "MIL, HOLES" at 13012.46,5380.71 h60
  text "+/-" at 12620,5380 h60
  text "+/-" at 13474,5380 h60
  text "REGISTRATION TOLERANCES:" at 11104.23,5375 h60
  text "METAL" at 12304,5375 h60
  text "5" at 12880.2,5375 h60
  text "3" at 13713.2,5375 h60
  text "MIL" at 13829.46,5375 h60
  text "+/-" at 13474,5262 h60
  text "HOLE SIZE TOLERANCE (UNLESS OTHERWISE SPECIFIED):" at 11104.23,5257 h60
  text "3" at 13713.2,5257 h60
  text "MIL" at 13829.46,5257 h60
  text "MATERIAL:" at 11029.46,5047.54 h60
  text "FR-4 High Tg" at 12015.9,4907.21 h60
  text "FR-408" at 11450.46,4898.64 h60
  text "OTHER" at 12938.46,4898.64 h60
  text "X" at 11861,4895 h60
  text "62 MIL (1.6mm) +/-10%" at 11770.56,4735.92 h60
  text "THICKNESS:" at 11104.23,4731.64 h60
  text "X" at 11642.4,4731.64 h60
  text "OTHER" at 13055.46,4731.64 h60
  text "TOLERANCE:" at 11104.23,4573.64 h60
  text "X" at 11943.53,4573.64 h60
  text "ANSI IPC-6012 TYPE 3 CLASS 2" at 12130.48,4573.64 h60
  text "OTHER +/-" at 12130.46,4417.64 h60
  text "BOW & TWIST:" at 11104.23,4260.64 h60
  text "X" at 11943.53,4260.64 h60
  text "ANSI IPC-6012 TYPE 3 CLASS 2" at 12130.48,4260.64 h60
  text "OTHER +/-" at 12130.46,4102.13 h60
  text "DRILLING:" at 11029.46,3963.64 h60
  text "REFERENCE:" at 11104.23,3846.64 h60
  text "X" at 11752.46,3846.64 h60
  text "AS SHOWN" at 11939.46,3846.64 h60
  text "X" at 12653.46,3846.64 h60
  text "NC_DRILL FILES" at 12790.46,3846.64 h60
  text "PTH MIN COPPER THICKNESS:" at 11104.23,3688.64 h60
  text "X" at 12454.46,3688.64 h60
  text "1MIL" at 12591.46,3688.64 h60
  text "OTHER" at 13088.46,3688.64 h60
  text "BOARD FINISH:" at 11029.46,3529.64 h60
  text "SILKSCREEN:" at 11184.68,3411.64 h60
  text "X" at 12133.46,3411.64 h60
  text "TOP" at 12259.46,3411.64 h60
  text "X" at 12643.46,3411.64 h60
  text "BOTTOM" at 12770.46,3411.64 h60
  text "SILKSCREEN COLOR:" at 11184.68,3244.64 h60
  text "X" at 12132.42,3244.64 h60
  text "WHITE" at 12259.46,3244.64 h60
  text "OTHER" at 12770.46,3244.64 h60
  text "X" at 12263.42,3085.44 h60
  text "GREEN" at 12390.46,3085.44 h60
  text "OTHER" at 13008.46,3085.44 h60
  text "SOLDER RESIST COLOR:" at 11184.68,3074.64 h60
  text "X" at 12263.42,2915.44 h60
  text "MATTE" at 12390.46,2915.44 h60
  text "SEMI-GLOSS" at 13008,2914.8 h60
  text "IMMERSION GOLD (ENIG)" at 12090.46,2726.92 h60
  text "ENEPIG" at 13428,2723.64 h60
  text "SURFACE FINISH:" at 11029.46,2722.64 h60
  text "X" at 11903.51,2722.64 h60
  text "IMM. TIN/SILVER OR EQUIV" at 11359,2565.64 h60
  text "OTHER" at 12790.46,2565.64 h60
  text "ARRAY/PANEL:" at 11029.46,2386.64 h60
  text "CUT AND TRIM PER M1 BOARD OUTLINE" at 12090.46,2382.35 h60
  text "N.C. ROUTE" at 12090.46,2230.64 h60
  text "X" at 12769.46,2230.64 h60
  text "V. SCORE" at 12956.46,2230.64 h60
  text "CERTIFICATION:" at 11029.46,2093.64 h60
  text "MATERIALS AND WORKMANSHIP FOR ALL PCBS" at 11754.46,2093.64 h60
  text "TO MEET OR EXCEED THE REQUIREMENTS OF:" at 11754.46,1995.64 h60
  text "X" at 11380.96,1859.13 h60
  text "ANSI IPC-A-600F CLASS ->" at 11519.96,1859.13 h60
  text "X" at 13159.02,1859.13 h60
  text "2" at 13277.96,1859.14 h60
  text "1" at 12962.96,1857.64 h60
  text "3" at 13631.96,1857.64 h60
  text "X" at 12195.02,1699.64 h60
  text "RoHS" at 12331.96,1699.64 h60
  text "OTHER" at 12976.36,1699.64 h60
  text "PER ORDER" at 13373.42,1699.64 h60
  text "ALL BOARDS MUST MEET OR EXCEED UL94-V0 REQUIREMENTS." at 11057,1534 h60
  text "PCB MUST BEAR THE UL94V-0 UL REGISTERED MATERIAL ID NUMBER" at 11057,1414 h60
  text "ADDITIONAL REQUIREMENTS:" at 11029.46,1240.64 h60
  text "MICROSECTION:" at 11104.23,1125.64 h60
  text "YES" at 12009.96,1125.64 h60
  text "REQUIRED" at 12871.46,969.49 h60
  text "BARE BOARD ELEC. TEST:" at 11104.23,966.64 h60
  text "NONE" at 12409.96,966.64 h60
  text "X" at 12744.46,966.64 h60
  text "PER ORDER" at 13463.46,966.64 h60
  text ".Layer_Name" at 277,-858.49 h60
M11 Gerber Information:
  lines w10: -592,-930.17 6008,-930.17 ; -592,-726.83 6010,-726.83 ; -592,-523.5 -592,-1133.5 3413,-1133.5 6010,-1133.5 6010,-523.5 -591.5,-523.5 -591.5,-1133.5 984,-1133.5 ; 1873,-1133.5 1873,-523.5 ; 3140,-726.83 3140,-523.5 ; 3980,-726.83 3980,-523.5 ; 4602,-1140 4602,-937.17
  text "ALL ARTWORK VIEWED FROM TOP SIDE" at -528.5,-655.67 h60
  text "BOARD #:" at 1948,-655.67 h60
  text ".PRJ_Number" at 2493.5,-655.67 h60
  text "REV:" at 3338,-655.67 h60
  text ".PCB_Rev" at 3629.5,-655.67 h60
  text "SVN REV:" at 4176,-655.67 h60
  text ".VersionControl_RevNumber" at 4682,-655.67 h60
  text "LAYER NAME =" at -528.5,-858.49 h60
  text "TID #:" at 1948,-859 h60
  text ".TID" at 2493.5,-859 h60
  text "PLOT NAME =" at -528.5,-1064.34 h60
  text ".plot_File_Name" at 277,-1064.34 h60
  text "GENERATED    :" at 1950,-1064.34 h60
  text ".Print_Date" at 2819.5,-1064.34 h60
  text ".Print_Time" at 3548.5,-1064.34 h60
  text "TEXAS INSTRUMENTS" at 4813,-1064.34 h60
M12 Stackup:
  drawing of 191 lines, arcs and shapes, not listed
  text "Layer" at 9490.34,7830 h60
  text "Name" at 9900.26,7830 h60
  text "Material" at 10830,7830 h60
  text "Thickness" at 11689.77,7830 h60
  text "Constant" at 12339.6,7830 h60
  text "Board Layer Stack" at 12909.46,7830 h60
  text "1" at 9490.34,7710 h60
  text "Top Overlay" at 9900.26,7710 h60
  text "2" at 9490.34,7590 h60
  text "Top Solder" at 9900.26,7590 h60
  text "Solder Resist" at 10830,7590 h60
  text "0.40mil" at 11689.77,7590 h60
  text "3.5" at 12339.6,7590 h60
  text "3" at 9490.34,7470 h60
  text "Top Layer" at 9900.26,7470 h60
  text "Copper" at 10830,7470 h60
  text "1.40mil" at 11689.77,7470 h60
  text "4" at 9490.34,7350 h60
  text "Dielectric1" at 9900.26,7350 h60
  text "FR-4" at 10830,7350 h60
  text "59.20mil" at 11689.77,7350 h60
  text "4.8" at 12339.6,7350 h60
  text "5" at 9490.34,7230 h60
  text "Bottom Layer" at 9900.26,7230 h60
  text "Copper" at 10830,7230 h60
  text "1.40mil" at 11689.77,7230 h60
  text "6" at 9490.34,7110 h60
  text "Bottom Solder" at 9900.26,7110 h60
  text "Solder Resist" at 10830,7110 h60
  text "0.40mil" at 11689.77,7110 h60
  text "3.5" at 12339.6,7110 h60
  text "7" at 9490.34,6990 h60
  text "Bottom Overlay" at 9900.26,6990 h60
  text ".Layer_Name" at 277,-858.49 h60
M13 Component Bodies Top:
  text ".Layer_Name" at 277,-858.49 h60
M14 Component Bodies Bottom:
  text ".Layer_Name" at 277,-858.49 h60
M15 Courtyards Top:
  text ".Layer_Name" at 277,-858.49 h60
M16 Courtyards Bottom:
  text ".Layer_Name" at 277,-858.49 h60
Drill Drawing:
  text ".Layer_Name" at 277,-858.49 h60
M17 Embedded Cavity:
  text ".Layer_Name" at 277,-858.49 h60
M18 Embedded Assembly:
  text ".Layer_Name" at 277,-858.49 h60
M19 Embedded Keepout:
  text ".Layer_Name" at 277,-858.49 h60

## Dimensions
0,-400 to 1000,-400 on M2 Board Dimensions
